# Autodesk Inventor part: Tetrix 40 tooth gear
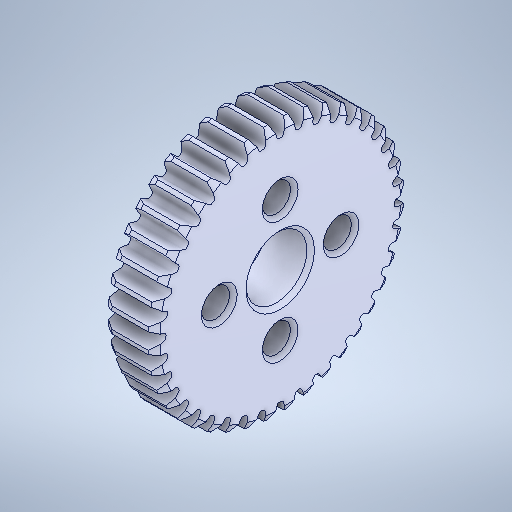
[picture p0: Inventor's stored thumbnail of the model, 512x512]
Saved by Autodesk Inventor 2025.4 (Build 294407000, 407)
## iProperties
Created: 2021-10
Part Number: Tetrix 40 tooth gear
Material: Genérico
Document SubType Name: Modeling
Designer: usuario
Density: 1 g/cm^3
Appearance: Valor por defecto
Author: usuario
Sending System: SolidWorks 2016
Last Author: LENOVO
Last Saved: 2021-10-21
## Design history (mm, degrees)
chamfer "Chamfer2"
node "Plane1"
node "Sólido1"
